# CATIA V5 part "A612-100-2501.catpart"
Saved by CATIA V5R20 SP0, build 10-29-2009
Part number: A612-100-2501
Source: Unknown
Property "A": "30.000"
Property "ARTICLENO": "A612-100-2501"
Property "B": "40.000"
Property "BOMINFO": "A612-100-2501"
Property "CODE": "A612-100-2501"
Property "D": "22.000"
Property "FORM": "B"
Property "L": "250.000"
Property "L1": "45.000"
Property "L2": "80.000"
Property "L3": "0.000"
Property "LINA": "A612-100-2501"
Property "NB": "A612-100-2501"
Property "NBSYN": "$CODE."
Property "NN": "A612"
Property "NT": "CDI 3357 E-Type Wear Plates, steel and self-lubricating"
Property "SUPPLIER": "CF"
Property "T": "30.000"
Property "W": "100.000"
Bounding box of the stored display mesh (mm): x 0 to 30, y 0 to 250, z 0 to 100
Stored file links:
  C:\Users\Utente\Desktop\3D files A612\A612-100-2501.catpart
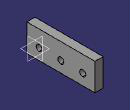
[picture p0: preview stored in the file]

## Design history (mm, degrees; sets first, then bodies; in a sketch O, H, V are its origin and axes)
Body1 "Geometry.1" (main body)
  Solid1 "A612-100-2501.catpart": solid without history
